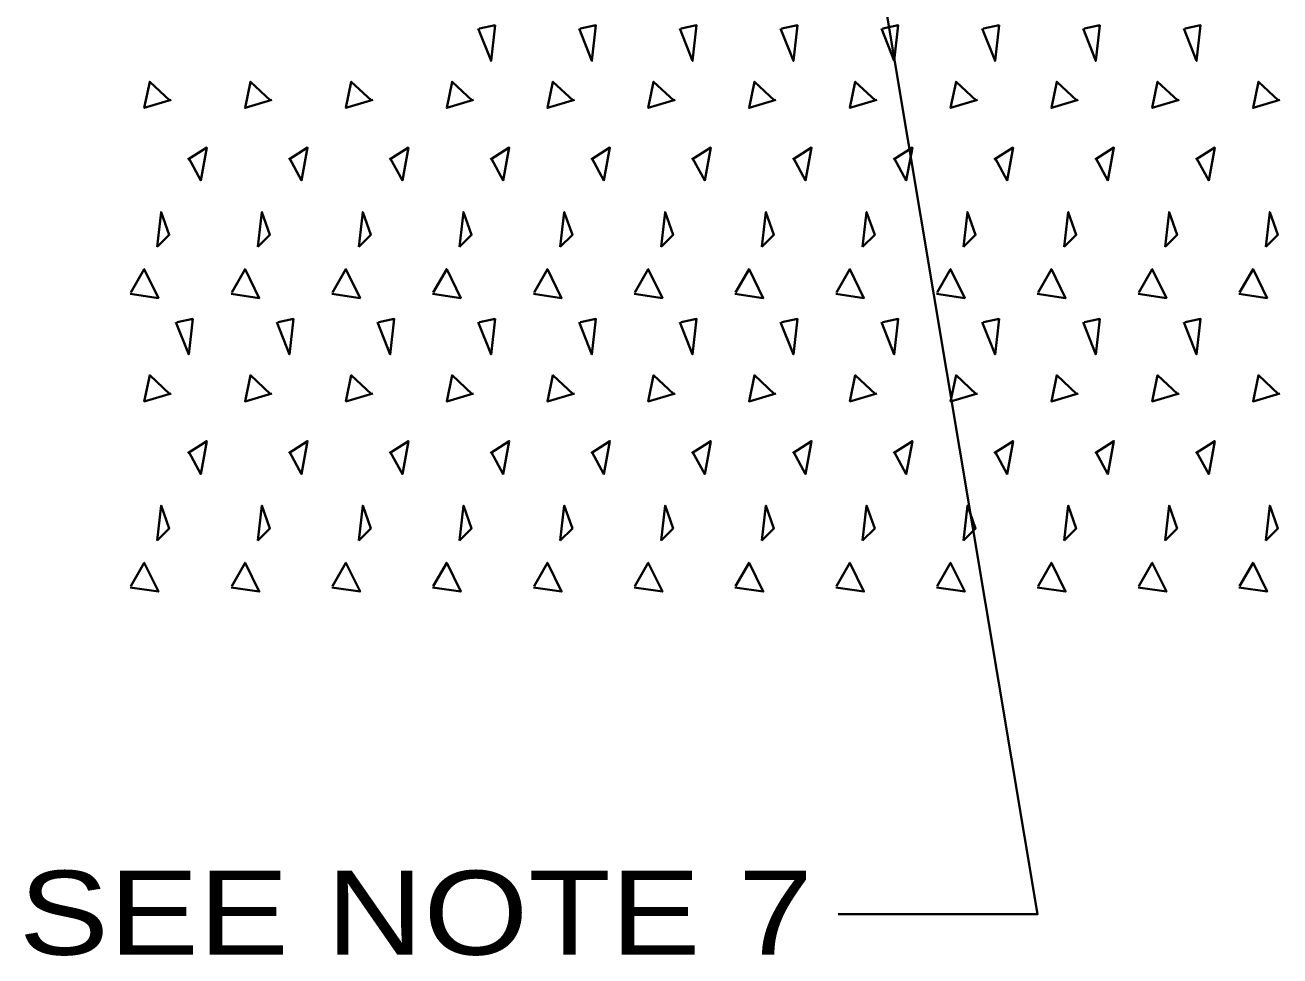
# Model space of a CAD drawing. Extents: x 918 to 1774, y -8 to 536.
# Drawn here: x 1057.66 to 1102.48, y 96.59 to 129.84 of the extents above; entities that cross this region are included whole.
import ezdxf

# ---------------------------------------------------------------- set-up
doc = ezdxf.new("R2010")
doc.units = 0
doc.header["$LTSCALE"] = 1.2
doc.layers.add('1', color=7, linetype='Continuous', lineweight=35)

msp = doc.modelspace()

# ---------------------------------------------------------------- linework, layer by layer
at = {"layer": '1'}
for points in [[(1084.092, 156.215), (1093.824, 98.076), (1086.695, 98.076)], [(1073.846, 129.711), (1074.302, 128.559), (1074.446, 129.831), (1073.894, 129.711)], [(1077.446, 129.711), (1077.902, 128.559), (1078.046, 129.831), (1077.494, 129.711)], [(1081.046, 129.711), (1081.502, 128.559), (1081.646, 129.831), (1081.094, 129.711)], [(1084.646, 129.711), (1085.102, 128.559), (1085.246, 129.831), (1084.694, 129.711)], [(1088.246, 129.711), (1088.702, 128.559), (1088.846, 129.831), (1088.294, 129.711)], [(1091.846, 129.711), (1092.302, 128.559), (1092.446, 129.831), (1091.894, 129.711)], [(1095.446, 129.711), (1095.902, 128.559), (1096.046, 129.831), (1095.494, 129.711)], [(1099.046, 129.711), (1099.502, 128.559), (1099.646, 129.831), (1099.094, 129.711)], [(1062.878, 127.167), (1061.918, 126.879), (1062.11, 127.815), (1062.83, 127.143)], [(1066.478, 127.167), (1065.518, 126.879), (1065.71, 127.815), (1066.43, 127.143)], [(1070.078, 127.167), (1069.118, 126.879), (1069.31, 127.815), (1070.03, 127.143)], [(1073.678, 127.167), (1072.718, 126.879), (1072.91, 127.815), (1073.63, 127.143)], [(1077.278, 127.167), (1076.318, 126.879), (1076.51, 127.815), (1077.23, 127.143)], [(1080.878, 127.167), (1079.918, 126.879), (1080.11, 127.815), (1080.83, 127.143)], [(1084.478, 127.167), (1083.518, 126.879), (1083.71, 127.815), (1084.43, 127.143)], [(1088.078, 127.167), (1087.118, 126.879), (1087.31, 127.815), (1088.03, 127.143)], [(1091.678, 127.167), (1090.718, 126.879), (1090.91, 127.815), (1091.63, 127.143)], [(1095.278, 127.167), (1094.318, 126.879), (1094.51, 127.815), (1095.23, 127.143)], [(1098.878, 127.167), (1097.918, 126.879), (1098.11, 127.815), (1098.83, 127.143)], [(1102.478, 127.167), (1101.518, 126.879), (1101.71, 127.815), (1102.43, 127.143)], [(1063.502, 125.079), (1063.934, 124.287), (1064.15, 125.463), (1063.478, 125.031)], [(1067.102, 125.079), (1067.534, 124.287), (1067.75, 125.463), (1067.078, 125.031)], [(1070.702, 125.079), (1071.134, 124.287), (1071.35, 125.463), (1070.678, 125.031)], [(1074.302, 125.079), (1074.734, 124.287), (1074.95, 125.463), (1074.278, 125.031)], [(1077.902, 125.079), (1078.334, 124.287), (1078.55, 125.463), (1077.878, 125.031)], [(1081.502, 125.079), (1081.934, 124.287), (1082.15, 125.463), (1081.478, 125.031)], [(1085.102, 125.079), (1085.534, 124.287), (1085.75, 125.463), (1085.078, 125.031)], [(1088.702, 125.079), (1089.134, 124.287), (1089.35, 125.463), (1088.678, 125.031)], [(1092.302, 125.079), (1092.734, 124.287), (1092.95, 125.463), (1092.278, 125.031)], [(1095.902, 125.079), (1096.334, 124.287), (1096.55, 125.463), (1095.878, 125.031)], [(1099.502, 125.079), (1099.934, 124.287), (1100.15, 125.463), (1099.478, 125.031)], [(1061.438, 120.279), (1061.918, 121.119), (1062.422, 120.087), (1061.414, 120.231)], [(1065.038, 120.279), (1065.518, 121.119), (1066.022, 120.087), (1065.014, 120.231)], [(1068.638, 120.279), (1069.118, 121.119), (1069.622, 120.087), (1068.614, 120.231)], [(1072.238, 120.279), (1072.718, 121.119), (1073.222, 120.087), (1072.214, 120.231)], [(1075.838, 120.279), (1076.318, 121.119), (1076.822, 120.087), (1075.814, 120.231)], [(1079.438, 120.279), (1079.918, 121.119), (1080.422, 120.087), (1079.414, 120.231)], [(1083.038, 120.279), (1083.518, 121.119), (1084.022, 120.087), (1083.014, 120.231)], [(1086.638, 120.279), (1087.118, 121.119), (1087.622, 120.087), (1086.614, 120.231)], [(1090.238, 120.279), (1090.718, 121.119), (1091.222, 120.087), (1090.214, 120.231)], [(1093.838, 120.279), (1094.318, 121.119), (1094.822, 120.087), (1093.814, 120.231)], [(1097.438, 120.279), (1097.918, 121.119), (1098.422, 120.087), (1097.414, 120.231)], [(1101.038, 120.279), (1101.518, 121.119), (1102.022, 120.087), (1101.014, 120.231)], [(1063.046, 119.223), (1063.502, 118.071), (1063.646, 119.343), (1063.094, 119.223)], [(1066.646, 119.223), (1067.102, 118.071), (1067.246, 119.343), (1066.694, 119.223)], [(1070.246, 119.223), (1070.702, 118.071), (1070.846, 119.343), (1070.294, 119.223)], [(1073.846, 119.223), (1074.302, 118.071), (1074.446, 119.343), (1073.894, 119.223)], [(1077.446, 119.223), (1077.902, 118.071), (1078.046, 119.343), (1077.494, 119.223)], [(1081.046, 119.223), (1081.502, 118.071), (1081.646, 119.343), (1081.094, 119.223)], [(1084.646, 119.223), (1085.102, 118.071), (1085.246, 119.343), (1084.694, 119.223)], [(1088.246, 119.223), (1088.702, 118.071), (1088.846, 119.343), (1088.294, 119.223)], [(1091.846, 119.223), (1092.302, 118.071), (1092.446, 119.343), (1091.894, 119.223)], [(1095.446, 119.223), (1095.902, 118.071), (1096.046, 119.343), (1095.494, 119.223)], [(1099.046, 119.223), (1099.502, 118.071), (1099.646, 119.343), (1099.094, 119.223)], [(1062.878, 116.679), (1061.918, 116.391), (1062.11, 117.327), (1062.83, 116.655)], [(1066.478, 116.679), (1065.518, 116.391), (1065.71, 117.327), (1066.43, 116.655)], [(1070.078, 116.679), (1069.118, 116.391), (1069.31, 117.327), (1070.03, 116.655)], [(1073.678, 116.679), (1072.718, 116.391), (1072.91, 117.327), (1073.63, 116.655)], [(1077.278, 116.679), (1076.318, 116.391), (1076.51, 117.327), (1077.23, 116.655)], [(1080.878, 116.679), (1079.918, 116.391), (1080.11, 117.327), (1080.83, 116.655)], [(1084.478, 116.679), (1083.518, 116.391), (1083.71, 117.327), (1084.43, 116.655)], [(1088.078, 116.679), (1087.118, 116.391), (1087.31, 117.327), (1088.03, 116.655)], [(1091.678, 116.679), (1090.718, 116.391), (1090.91, 117.327), (1091.63, 116.655)], [(1095.278, 116.679), (1094.318, 116.391), (1094.51, 117.327), (1095.23, 116.655)], [(1098.878, 116.679), (1097.918, 116.391), (1098.11, 117.327), (1098.83, 116.655)], [(1102.478, 116.679), (1101.518, 116.391), (1101.71, 117.327), (1102.43, 116.655)], [(1063.502, 114.591), (1063.934, 113.799), (1064.15, 114.975), (1063.478, 114.543)], [(1067.102, 114.591), (1067.534, 113.799), (1067.75, 114.975), (1067.078, 114.543)], [(1070.702, 114.591), (1071.134, 113.799), (1071.35, 114.975), (1070.678, 114.543)], [(1074.302, 114.591), (1074.734, 113.799), (1074.95, 114.975), (1074.278, 114.543)], [(1077.902, 114.591), (1078.334, 113.799), (1078.55, 114.975), (1077.878, 114.543)], [(1081.502, 114.591), (1081.934, 113.799), (1082.15, 114.975), (1081.478, 114.543)], [(1085.102, 114.591), (1085.534, 113.799), (1085.75, 114.975), (1085.078, 114.543)], [(1088.702, 114.591), (1089.134, 113.799), (1089.35, 114.975), (1088.678, 114.543)], [(1092.302, 114.591), (1092.734, 113.799), (1092.95, 114.975), (1092.278, 114.543)], [(1095.902, 114.591), (1096.334, 113.799), (1096.55, 114.975), (1095.878, 114.543)], [(1099.502, 114.591), (1099.934, 113.799), (1100.15, 114.975), (1099.478, 114.543)], [(1061.438, 109.791), (1061.918, 110.631), (1062.422, 109.599), (1061.414, 109.743)], [(1065.038, 109.791), (1065.518, 110.631), (1066.022, 109.599), (1065.014, 109.743)], [(1068.638, 109.791), (1069.118, 110.631), (1069.622, 109.599), (1068.614, 109.743)], [(1072.238, 109.791), (1072.718, 110.631), (1073.222, 109.599), (1072.214, 109.743)], [(1075.838, 109.791), (1076.318, 110.631), (1076.822, 109.599), (1075.814, 109.743)], [(1079.438, 109.791), (1079.918, 110.631), (1080.422, 109.599), (1079.414, 109.743)], [(1083.038, 109.791), (1083.518, 110.631), (1084.022, 109.599), (1083.014, 109.743)], [(1086.638, 109.791), (1087.118, 110.631), (1087.622, 109.599), (1086.614, 109.743)], [(1090.238, 109.791), (1090.718, 110.631), (1091.222, 109.599), (1090.214, 109.743)], [(1093.838, 109.791), (1094.318, 110.631), (1094.822, 109.599), (1093.814, 109.743)], [(1097.438, 109.791), (1097.918, 110.631), (1098.422, 109.599), (1097.414, 109.743)], [(1101.038, 109.791), (1101.518, 110.631), (1102.022, 109.599), (1101.014, 109.743)]]:
    msp.add_lwpolyline(points, dxfattribs=at)
for points in [[(1062.374, 121.911), (1062.518, 123.159), (1062.806, 122.343)], [(1065.974, 121.911), (1066.118, 123.159), (1066.406, 122.343)], [(1069.574, 121.911), (1069.718, 123.159), (1070.006, 122.343)], [(1073.174, 121.911), (1073.318, 123.159), (1073.606, 122.343)], [(1076.774, 121.911), (1076.918, 123.159), (1077.206, 122.343)], [(1080.374, 121.911), (1080.518, 123.159), (1080.806, 122.343)], [(1083.974, 121.911), (1084.118, 123.159), (1084.406, 122.343)], [(1087.574, 121.911), (1087.718, 123.159), (1088.006, 122.343)], [(1091.174, 121.911), (1091.318, 123.159), (1091.606, 122.343)], [(1094.774, 121.911), (1094.918, 123.159), (1095.206, 122.343)], [(1098.374, 121.911), (1098.518, 123.159), (1098.806, 122.343)], [(1101.974, 121.911), (1102.118, 123.159), (1102.406, 122.343)], [(1062.374, 111.423), (1062.518, 112.671), (1062.806, 111.855)], [(1065.974, 111.423), (1066.118, 112.671), (1066.406, 111.855)], [(1069.574, 111.423), (1069.718, 112.671), (1070.006, 111.855)], [(1073.174, 111.423), (1073.318, 112.671), (1073.606, 111.855)], [(1076.774, 111.423), (1076.918, 112.671), (1077.206, 111.855)], [(1080.374, 111.423), (1080.518, 112.671), (1080.806, 111.855)], [(1083.974, 111.423), (1084.118, 112.671), (1084.406, 111.855)], [(1087.574, 111.423), (1087.718, 112.671), (1088.006, 111.855)], [(1091.174, 111.423), (1091.318, 112.671), (1091.606, 111.855)], [(1094.774, 111.423), (1094.918, 112.671), (1095.206, 111.855)], [(1098.374, 111.423), (1098.518, 112.671), (1098.806, 111.855)], [(1101.974, 111.423), (1102.118, 112.671), (1102.406, 111.855)]]:
    msp.add_lwpolyline(points, close=True, dxfattribs=at)

# ---------------------------------------------------------------- texts
at = {"layer": '1', "width": 1.2}
msp.add_text('SEE NOTE 7', height=3, dxfattribs=at).set_placement((1057.441, 96.628))

doc.saveas('drawing.dxf')
